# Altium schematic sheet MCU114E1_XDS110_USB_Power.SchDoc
size 431 x 279 mm; Date: Not shown in title block; ApprovedBy: Not shown in title block; CheckedBy: Not shown in title block; Author: Not shown in title block; CompanyName: Not shown in title block; Engineer: Not shown in title block; Organization: Not shown in title block; Address1: Not shown in title block; Address2: Not shown in title block; Address3: Not shown in title block; Address4: Not shown in title block; DocumentNumber: 8; Revision: Use project parameter SCH_Rev; SheetNumber: 8; SheetTotal: 11; PageSetup: Record=PageOptions¦CenterHorizontal=True¦CenterVertical=True¦PrintScale=1.00¦XCorrection=1.00¦YCorrection=1.00¦PrintKind=0¦BorderSize=5000000¦LeftOffset=0¦BottomOffset=0¦Orientation=2¦PaperLength=1000¦PaperWidth=1000¦Scale=100¦PaperSource=15¦PrintQuality=600¦MediaType=1¦DitherType=10¦PaperKind=Letter¦PrintScaleMode=1
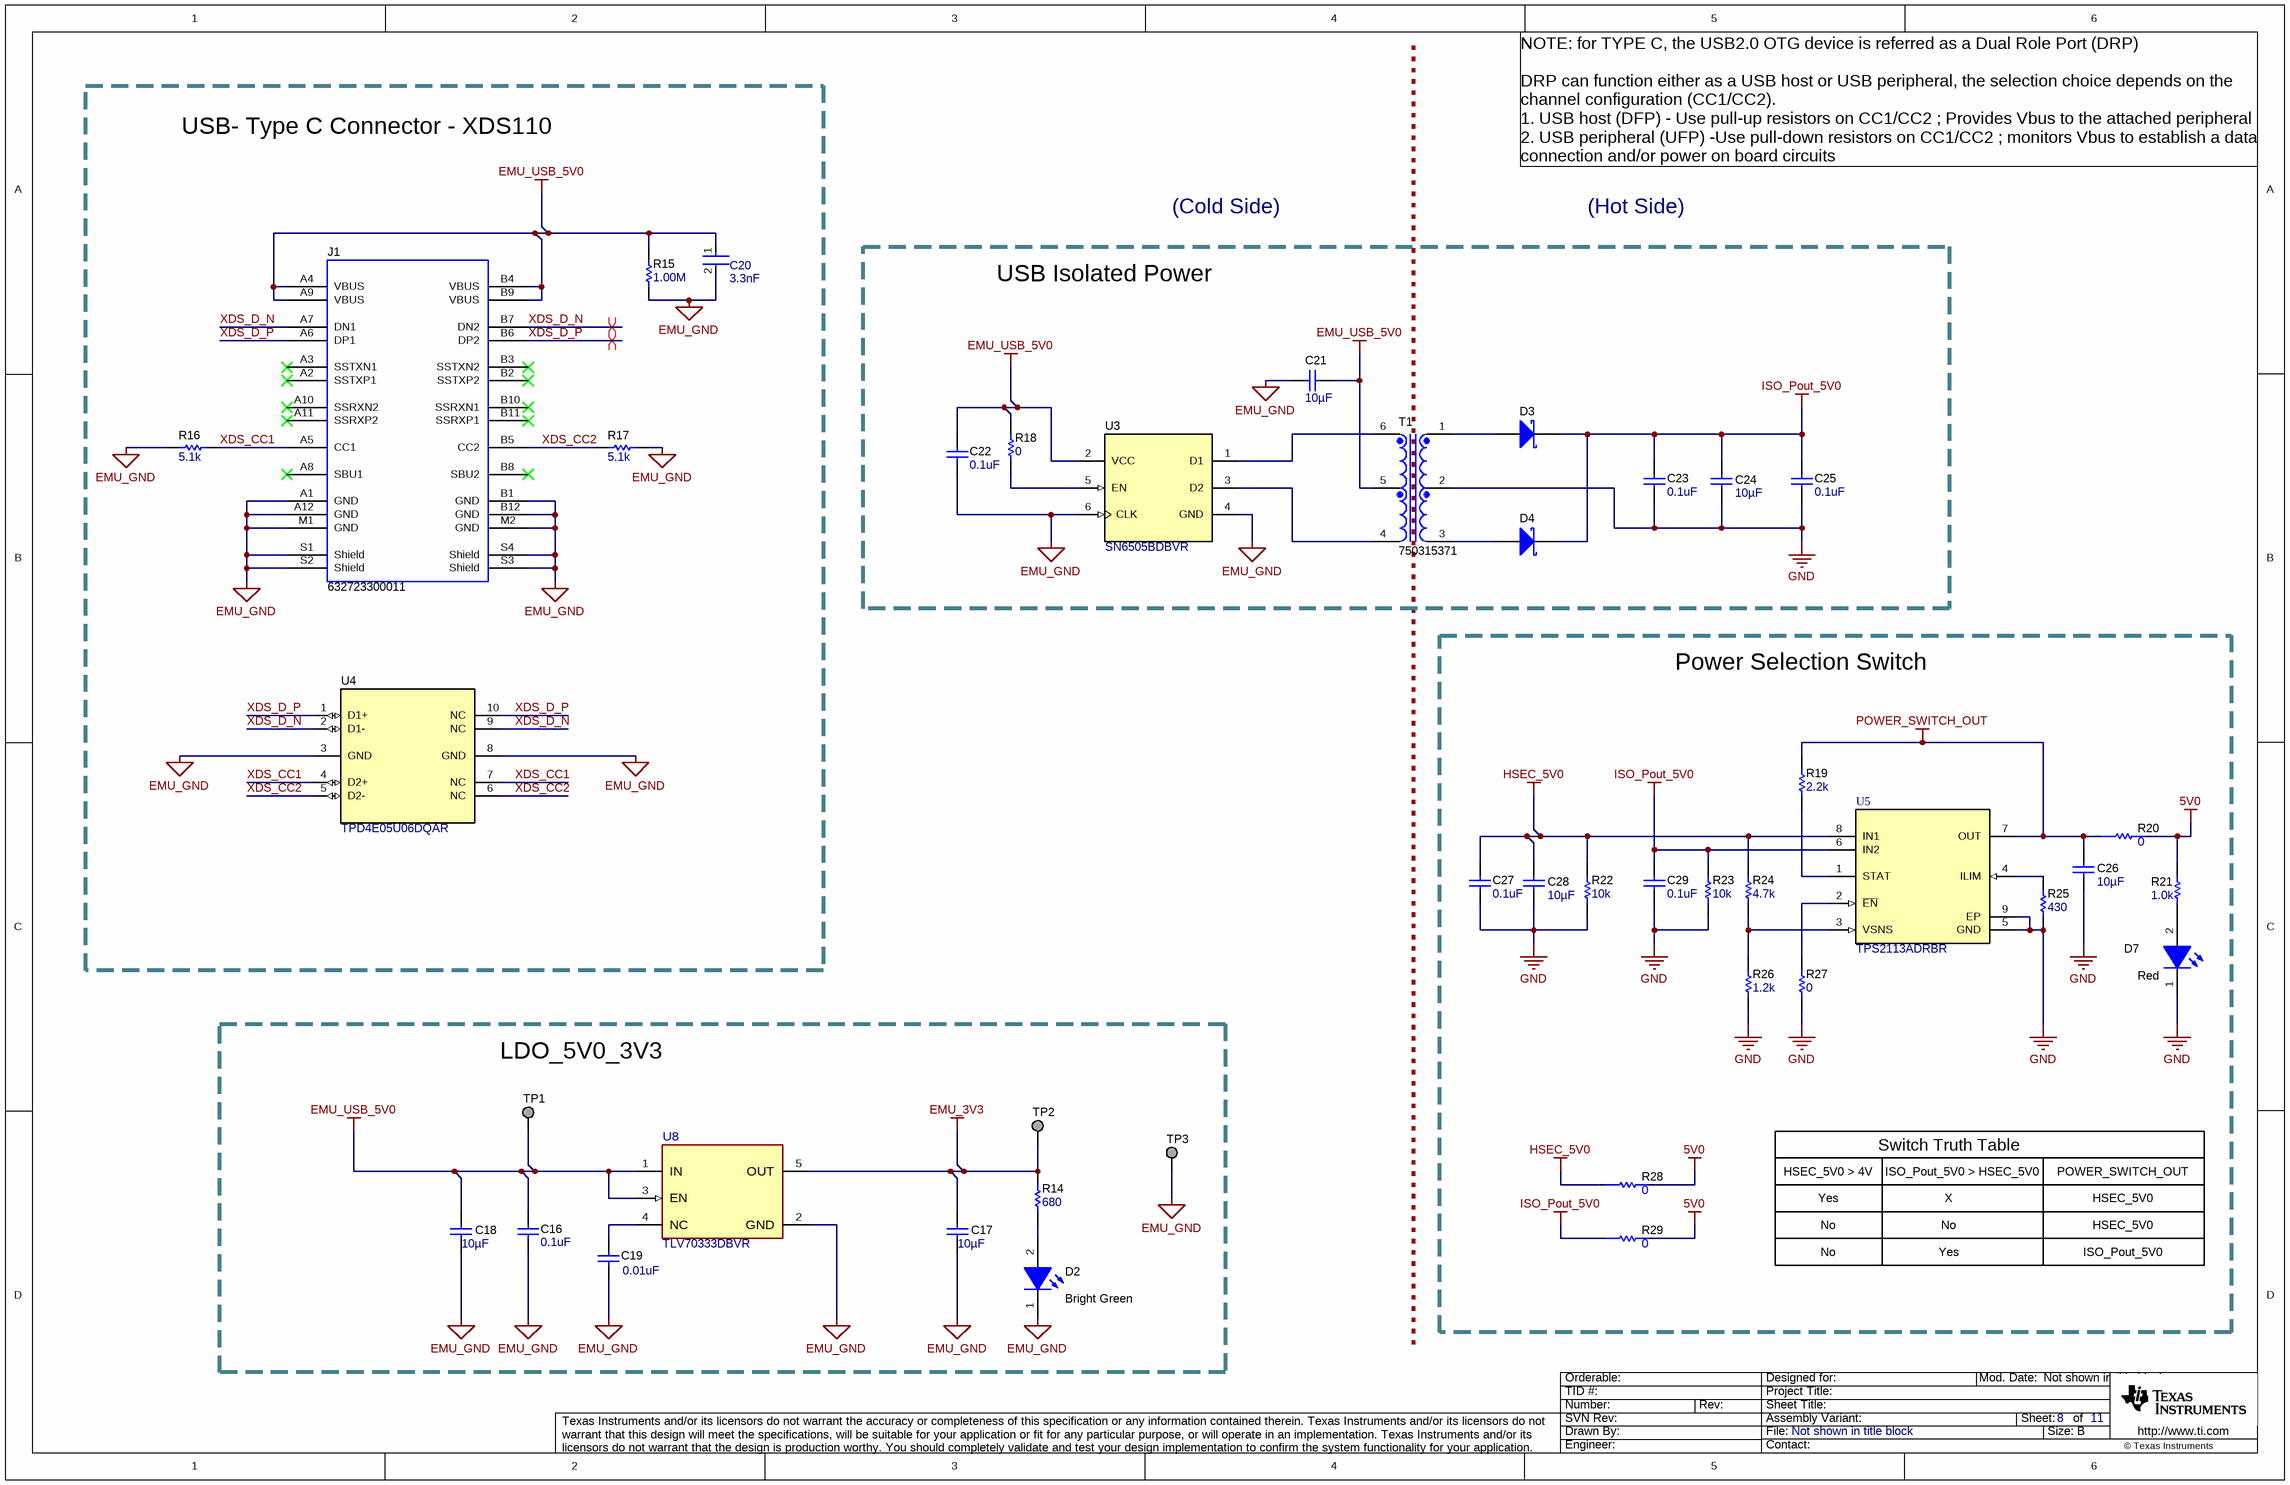
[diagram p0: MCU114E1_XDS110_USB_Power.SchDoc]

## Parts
C16  ValueDisplayed: 0.1uF  [0402]  (hidden comment: 885012205037)
C17  ValueDisplayed: 10µF  [0402_080]  (hidden comment: 0402ZD106MAT2A)
C18  ValueDisplayed: 10µF  [0402_080]  (hidden comment: 0402ZD106MAT2A)
C19  ValueDisplayed: 0.01uF  [0402]  (hidden comment: 885012205031)
C20  Capacitance: 3.3nF  [FP-CL388-IPC_C]  (hidden comment: CL05B332KB5NNNC)
C21  ValueDisplayed: 10µF  [0603]  (hidden comment: GRM188R61C106KAALD)
C22  ValueDisplayed: 0.1uF  [0402]  (hidden comment: 885012205037)
C23  ValueDisplayed: 0.1uF  [0402]  (hidden comment: 885012205037)
C24  ValueDisplayed: 10µF  [0603]  (hidden comment: GRM188R61C106KAALD)
C25  ValueDisplayed: 0.1uF  [0402]  (hidden comment: 885012205037)
C26  ValueDisplayed: 10µF  [0603]  (hidden comment: GRM188R61C106KAALD)
C27  ValueDisplayed: 0.1uF  [0402]  (hidden comment: 885012205037)
C28  ValueDisplayed: 10µF  [0603]  (hidden comment: GRM188R61C106KAALD)
C29  ValueDisplayed: 0.1uF  [0402]  (hidden comment: 885012205037)
D2  value Bright Green  [WL-SMCW_Green_0805]  (hidden comment: 150080VS75000)
D3  1N5819HW-7-F  [SOD-123]  (value not drawn)
D4  1N5819HW-7-F  [SOD-123]  (value not drawn)
D7  value Red  [WL-SMCW_RED_0805]  (hidden comment: 150080SS75000)
J1  632723300011  [Wurth_632_723_300_011]
R14  ValueDisplayed: 680  [0402]  (hidden comment: CRCW0402680RJNED)
R15  ValueDisplayed: 1.00M  [0402]  (hidden comment: RMCF0402FT1M00)
R16  ValueDisplayed: 5.1k  [0603]  (hidden comment: RC0603JR-075K1L)
R17  ValueDisplayed: 5.1k  [0603]  (hidden comment: RC0603JR-075K1L)
R18  ValueDisplayed: 0  [0603]  (hidden comment: ERJ-3GEY0R00V)
R19  ValueDisplayed: 2.2k  [0603]  (hidden comment: CRCW06032K20JNEA)
R20  0  [FP-MCT0603MZ0000ZP500_0603-MFG]
R21  ValueDisplayed: 1.0k  [0603]  (hidden comment: RCA06031K00JNEA)
R22  ValueDisplayed: 10k  [0603]  (hidden comment: CRCW060310K0JNEA)
R23  ValueDisplayed: 10k  [0603]  (hidden comment: CRCW060310K0JNEA)
R24  ValueDisplayed: 4.7k  [0603]  (hidden comment: RC0603JR-074K7L)
R25  ValueDisplayed: 430  [0603]  (hidden comment: RC0603FR-07430RL)
R26  ValueDisplayed: 1.2k  [0603]  (hidden comment: RC0603JR-071K2L)
R27  ValueDisplayed: 0  [0603]  (hidden comment: ERJ-3GEY0R00V)
R28  0  [FP-MCT0603MZ0000ZP500_0603-MFG]
R29  0  [FP-MCT0603MZ0000ZP500_0603-MFG]
T1  750315371  [Wurth_750315371]
TP1  TESTPOINT  [TP_50MIL-25MILHOLE]  (value not drawn)  (no BOM)
TP2  TESTPOINT  [TP_50MIL-25MILHOLE]  (value not drawn)  (no BOM)
TP3  TESTPOINT  [TP_50MIL-25MILHOLE]  (value not drawn)  (no BOM)
U3  SN6505BDBVR  [DBV0006A_L]
U4  TPD4E05U06DQAR  [DQA0010A]
U5  TPS2113ADRBR  [DRB0008B]
U8  TLV70333DBVR  [DBV0005A-MFG]

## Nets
5V0: R20.2 R21.2 R28.2 R29.2
EMU_3V3: C17.1 R14.1 TP2.1 U8.5(OUT)
EMU_GND: C16.2 C17.2 C18.2 C19.2 C20.2 C21.1 C22.2 D2.1(K) J1.A1(GND) J1.A12(GND) J1.B1(GND) J1.B12(GND) J1.M1(GND) J1.M2(GND) J1.S1(Shield) J1.S2(Shield) J1.S3(Shield) J1.S4(Shield) R15.1 R16.1 R17.2 TP3.1 U3.4(GND) U3.6(CLK) U4.3(GND) U4.8(GND) U8.2(GND)
EMU_USB_5V0: C16.1 C18.1 C20.1 C21.2 C22.1 J1.A4(VBUS) J1.A9(VBUS) J1.B4(VBUS) J1.B9(VBUS) R15.2 R18.2 T1.5 TP1.1 U3.2(VCC) U8.1(IN) U8.3(EN)
GND: C23.2 C24.2 C25.2 C26.2 C27.2 C28.2 C29.2 D7.1(K) R22.1 R23.1 R25.1 R26.1 R27.1 T1.2 U5.5(GND) U5.9(EP)
HSEC_5V0: C27.1 C28.1 R22.2 R24.2 R28.1 U5.8(IN1)
ISO_Pout_5V0: C23.1 C24.1 C25.1 C29.1 D3.1(K) D4.1(K) R23.2 R29.1 U5.6(IN2)
POWER_SWITCH_OUT: C26.1 R19.2 R20.1 U5.7(OUT)
XDS_CC1: J1.A5(CC1) R16.2 U4.4(D2+) U4.7(NC)
XDS_CC2: J1.B5(CC2) R17.1 U4.5(D2-) U4.6(NC)
XDS_D_N: J1.A7(DN1) J1.B7(DN2) U4.2(D1-) U4.9(NC)
XDS_D_P: J1.A6(DP1) J1.B6(DP2) U4.1(D1+) U4.10(NC)
NetC19_1: C19.1 U8.4(NC)
NetD2_2: D2.2(A) R14.2
NetD3_2: D3.2(A) T1.1
NetD4_2: D4.2(A) T1.3
NetD7_2: D7.2(A) R21.1
NetR18_1: R18.1 U3.5(EN)
NetR19_1: R19.1 U5.1(STAT)
NetR24_1: R24.1 R26.2 U5.3(VSNS)
NetR25_2: R25.2 U5.4(ILIM)
NetR27_2: R27.2 U5.2(~{EN})
NetT1_4: T1.4 U3.3(D2)
NetT1_6: T1.6 U3.1(D1)

Not connected (* = marked no-connect by the designer): J1 A2(SSTXP1)* A3(SSTXN1)* A8(SBU1)* A10(SSRXN2)* A11(SSRXP2)* B2(SSTXP2)* B3(SSTXN2)* B8(SBU2)* B10(SSRXN1)* B11(SSRXP1)*

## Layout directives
differential pair: XDS_D_N, XDS_D_P

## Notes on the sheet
- USB- Type C Connector - XDS110
- NOTE: for TYPE C, the USB2.0 OTG device is referred as a Dual Role Port (DRP)
  DRP can function either as a USB host or USB peripheral, the selection choice depends on the channel configuration (CC1/CC2).
  1. USB host (DFP) - Use pull-up resistors on CC1/CC2 ; Provides Vbus to the attached peripheral
  2. USB peripheral (UFP) -Use pull-down resistors on CC1/CC2 ; monitors Vbus to establish a data connection and/or power on board circuits
- (Cold Side)
- (Hot Side)
- USB Isolated Power
- Power Selection Switch
- LDO_5V0_3V3
- HSEC_5V0 > 4V
- Switch Truth Table
- ISO_Pout_5V0 > HSEC_5V0
- POWER_SWITCH_OUT
- Yes
- No
- X
- HSEC_5V0
- ISO_Pout_5V0

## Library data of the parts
C16 C22 C23 C25 C27 C29 = CMP-0006228-2: CAP, CERM, 0.1 uF, 16 V, +/- 10%, X7R, 0402; Manufacturer: Wurth Elektronik; TaMin_C: -55°C; Polarized: N; SizeAreaWB_mm2: 3; Value1: Unknown; U/M: EA; Value: 0.1uF; TaMax_C: 125°C; SizeZ_mm: 0.6; SizeX_mm: 1; SizeY_mm: 0.5; Value2: 16V; Cap_F: 100nF; AEC Category: Q200
C17 C18 = CMP-0078623-1: CAP, CERM, 10 µF, 10 V,+/- 20%, X5R, 0402; Manufacturer: AVX; SizeAreaWB_mm2: 3; SizeArea_mm2: 0.5; AEC Qualified: N; AEC Category: Q200; Value: 10uF; TaMax_C: 85°C; SizeZ_mm: 0.8; TaMin_C: -55°C; VDC_V: 10V; U/M: EA; SizeX_mm: 1
C19 = CMP-0006227-2: CAP, CERM, 0.01 uF, 16 V, +/- 10%, X7R, 0402; Manufacturer: Wurth Elektronik; TaMin_C: -55°C; Polarized: N; SizeAreaWB_mm2: 3; Value1: Unknown; U/M: EA; Value: 0.01uF; TaMax_C: 125°C; SizeZ_mm: 0.6; SizeX_mm: 1; SizeY_mm: 0.5; Value2: 16V; Cap_F: 10nF; AEC Category: Q200
C20 = CMP-13271-000627-1: Cap Ceramic 3.3nF 50V X7R ±10% SMD 0402 +125°C Paper T/R
C21 C24 C26 C28 = CMP-0086225-1: CAP, CERM, 10 µF, 16 V,+/- 10%, X5R, 0603; Manufacturer: MuRata; SizeZ_mm: 1; SizeX_mm: 1.6; SizeArea_mm2: 1.28; VDC_V: 16V; U/M: EA; AEC Category: Q200; SizeY_mm: 0.8; Polarized: N; TaMax_C: 85°C; Value: 10uF; SizeAreaWB_mm2: 4.68; TaMin_C: -55°C
D2 = CMP-0002960-2: LED, Bright Green, SMD; Manufacturer: Wurth Elektronik; Type: AlInGaP; Vf_V: 2V; Io_A: 20mA; Vr_V: 5V; Tjmax_C: 85°C; Power_TotalModule: 72mW; Value1: 0.072W; Angle: 140; U/M: EA
D3 D4 = CMP-0028360-2: Diode, Schottky, 40 V, 1 A, SOD-123; Manufacturer: Diodes Inc.; Green_Lifecycle: Active; AEC Category: Q101; TJmax_C: 125°C; SizeArea_mm2: 6.545; Vr_V: 40V; Value1: 1A; SizeZ_mm: 1.35; Value: 40V; Vf_V: 450mV; SizeX_mm: 3.85; Green_REACh: Passed; Value2: 0.45V; SizeY_mm: 1.7; SizeAreaWB_mm2: 13.095
D7 = CMP-0002951-3: LED, Red, SMD; Manufacturer: Wurth Elektronik; Type: AlInGaP; Angle: 140; Vr_V: 5V; Ir_A: 25µA; Vf_V: 1.9V; Value1: 0.072W; Tjmax_C: 85°C; Io_A: 30mA; Power_TotalModule: 72mW
J1 = CMP-0080891-1: Connector, Receptacle, USB Type C, R/A; Manufacturer: Wurth Elektronik; Current_A: 3A; Gender: Female; Voltage_V: 5V; ContactFinish: Gold; Cert_UL: Y
R14 = CMP-0026962-3: RES, 680, 5%, 0.063 W, AEC-Q200 Grade 0, 0402; Manufacturer: Vishay-Dale; Value: 680; Value_Code: 680R; Power_W: 63mW; Value2: 0.063W; VDC_V: 50V; TempCo: 200 ppm/C; EIA_Code: E24; AEC Category: Q200; AEC Qualified: Y; AEC Grade: 0; SizeArea_mm2: 0.5; SizeX_mm: 1; SizeZ_mm: 0.6
R15 = CMP-0026757-1: RES, 1.00 M, 1%, 0.063 W, AEC-Q200 Grade 0, 0402; Manufacturer: Stackpole Electronics Inc; Power_W: 63mW; TempCo: 100 ppm/C; Value_Code: 1M00; U/M: EA; Value: 1.00Meg; EIA_Code: E96; Res_ohm: 1M; SizeX_mm: 1; SizeY_mm: 0.5; SizeZ_mm: 0.6; Value2: 0.063W; AEC Qualified: Y; VDC_V: 50V; AEC Grade: 0; AEC Category: Q200
R16 R17 = CMP-0025932-5: RES, 5.1 k, 5%, 0.1 W, 0603; Manufacturer: Yageo; Power_W: 100mW; TempCo: 100 ppm/C; Value_Code: 5k10; Value: 5.1k; EIA_Code: E24; SizeX_mm: 1.6; SizeY_mm: 0.8; SizeZ_mm: 1; Value2: 0.1W; SizeArea_mm2: 1.28; AEC Qualified: N; VDC_V: 75V; AEC Category: Q200; SizeAreaWB_mm2: 4.68
R18 R27 = CMP-0025874-4: RES, 0, 5%, 0.1 W, AEC-Q200 Grade 0, 0603; Manufacturer: Panasonic; Power_W: 100mW; TempCo: 600 ppm/C; Value_Code: 0000; Value: 0; EIA_Code: E24; SizeX_mm: 1.6; SizeY_mm: 0.8; SizeZ_mm: 1; Value2: 0.1W; SizeArea_mm2: 1.28; AEC Qualified: Y; VDC_V: 50V; AEC Category: Q200; SizeAreaWB_mm2: 4.68
R19 = CMP-0025769-4: RES, 2.2 k, 5%, 0.1 W, AEC-Q200 Grade 0, 0603; Manufacturer: Vishay-Dale; Power_W: 100mW; TempCo: 200 ppm/C; Value_Code: 2k20; Value: 2.2k; EIA_Code: E24; SizeX_mm: 1.6; SizeY_mm: 0.8; SizeZ_mm: 1; Value2: 0.1W; SizeArea_mm2: 1.28; AEC Qualified: Y; VDC_V: 75V; AEC Category: Q200; AEC Grade: 0
R20 R28 R29 = CMP-0096493-1: 15; Manufacturer: Vishay; Part Number: MCT0603MZ0000ZP500; VDC_V: 75V; Power_W: 150mW; AEC Qualified: Yes; SizeZ_mm: 0.55mm
R21 = CMP-0025946-3: RES, 1.0 k, 5%, 0.1 W, AEC-Q200 Grade 0, 0603; Manufacturer: Vishay-Dale; Power_W: 100mW; TempCo: 200 ppm/C; Value_Code: 1k00; U/M: EA; Value: 1.0k; EIA_Code: E24; Res_ohm: 1k; SizeX_mm: 1.6; SizeY_mm: 0.8; SizeZ_mm: 1; Value2: 0.1W; SizeArea_mm2: 1.28; AEC Qualified: Y; VDC_V: 75V; AEC Grade: 0; AEC Category: Q200
R22 R23 = CMP-0025701-4: RES, 10 k, 5%, 0.1 W, AEC-Q200 Grade 0, 0603; Manufacturer: Vishay-Dale; Power_W: 100mW; TempCo: 200 ppm/C; Value_Code: 10k0; Value: 10k; EIA_Code: E24; SizeX_mm: 1.6; SizeY_mm: 0.8; SizeZ_mm: 1; Value2: 0.1W; SizeArea_mm2: 1.28; AEC Qualified: Y; VDC_V: 75V; AEC Category: Q200; AEC Grade: 0
R24 = CMP-0025927-5: RES, 4.7 k, 5%, 0.1 W, 0603; Manufacturer: Yageo; Power_W: 100mW; TempCo: 100 ppm/C; Value_Code: 4k70; Value: 4.7k; EIA_Code: E24; SizeX_mm: 1.6; SizeY_mm: 0.8; SizeZ_mm: 1; Value2: 0.1W; SizeArea_mm2: 1.28; AEC Qualified: N; VDC_V: 75V; AEC Category: Q200; SizeAreaWB_mm2: 4.68
R25 = CMP-0023109-5: RES, 430, 1%, 0.1 W, 0603; Manufacturer: Yageo; Power_W: 100mW; TempCo: 100 ppm/C; Value_Code: 430R; Value: 430; SizeX_mm: 1.6; SizeY_mm: 0.8; SizeZ_mm: 1; Value2: 0.1W; SizeArea_mm2: 1.28; AEC Qualified: N; VDC_V: 75V; AEC Category: Q200; SizeAreaWB_mm2: 4.68
R26 = CMP-0025894-5: RES, 1.2 k, 5%, 0.1 W, 0603; Manufacturer: Yageo; Power_W: 100mW; TempCo: 100 ppm/C; Value_Code: 1k20; Value: 1.2k; EIA_Code: E24; SizeX_mm: 1.6; SizeY_mm: 0.8; SizeZ_mm: 1; Value2: 0.1W; SizeArea_mm2: 1.28; AEC Qualified: N; VDC_V: 75V; AEC Category: Q200; SizeAreaWB_mm2: 4.68
T1 = CMP-0030623-1: Transformer, 105uH, TH; Manufacturer: Wurth Elektronik; Green_Lifecycle: Active; DCR_ohm: 60m; Green_REACh: Passed; Lp: 105; Ns1toNp: 1.1; Ind_H: 105µH
TP1-TP3 = CMP-0078143-3: TEST POINT.  No entry in BOM.
U3 = CMP-0076095-1: Low-Noise 1 A, 420 kHz Transformer Driver, DBV0006A (SOT-23-6); Manufacturer: Texas Instruments; Alternate PartNumber: SN6505BDBVT; SizeAreaWB_mm2: 14.82; SizeArea_mm2: 8.12; SizeZ_mm: 1.45; Green_REACh: Passed; SizeY_mm: 2.9; Green_Lifecycle: Active; U/M: EA; CompType: IC; SizeX_mm: 2.8
U4 = CMP-0073613-3: 4-Channel Ultra-Low-Capacitance IEC ESD Protection Diode, DQA0010A (USON-10); Alternate Manufacturer: Texas Instruments; Green_Lifecycle: Active; SizeAreaWB_mm2: 7.0; Green_REACh: Passed; SizeZ_mm: 0.55; SizeX_mm: 1.0; SizeY_mm: 2.5; CompType: IC; AEC Category: Q200; AEC Qualified: N
U5 = CMP-0043361-3: Dual In / Single Out Autoswitching Power Mux, 2.8 to 5.5 V, -40 to 85 degC, 9-pin SON (DRB), Green (RoHS & no Sb/Br); Manufacturer: Texas Instruments; SubFamily: Power Multiplexer (MUX); IN1 Output Current(Max)(A): 1.25; IN1, IN2 Input Voltage(Min)(V): 2.8; IN2 rDS(on)(Typ)(Ohms): 0.084; Number of Inputs: 2; IN1, IN2 Input Voltage(Max)(V): 5.5; IN1 rDS(on)(Typ)(mOhm): 84; AEC Category: Q200; AEC Qualified: N; CompType: IC; SizeAreaWB_mm2: 16.0; SizeArea_mm2: 9.0; SizeX_mm: 3.0; SizeZ_mm: 1.0
U8 = CMP-0091939-1: Linear Voltage Regulator IC Positive Fixed 1 Output 300mA SOT-23-5; Manufacturer: Texas Instruments; SizeZ_mm: 1.45mm; Nominal Supply Current: 35-370uA; TJmax_C: +125°C; Output Voltage: 3.3V; Dropout Voltage: 260mV; Standoff Height: 0mm; Accuracy Percentage: 2%; AEC Qualified: No; Max Supply Voltage: 5.5V; Number Of Outputs: 1; Min Supply Voltage: 2V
